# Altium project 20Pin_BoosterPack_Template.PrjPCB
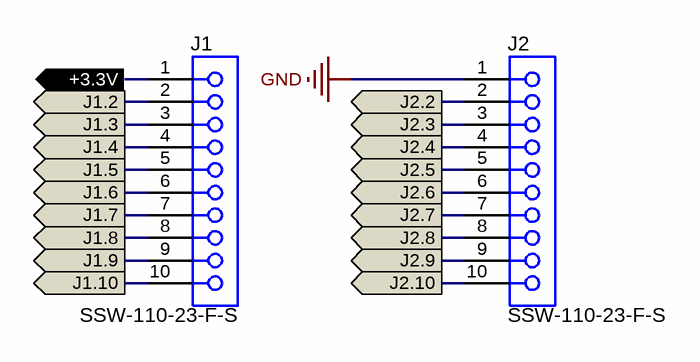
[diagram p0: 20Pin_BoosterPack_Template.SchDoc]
CopyrightYear: 2012; PCB_Layout: Who did the Layout?; PCB_Rev: E1; PRJ_Customer: Public Release; PRJ_Engineer: Enter name of project lead; PRJ_Number: XX####; PRJ_Title: Change in menu Project|Project Options|Parameters; SCH_Rev: E1; TechSupport: http://www.ti.com/support
1 sheet, 2 parts. Net scope: flat (ports and power ports of the same name join across sheets).
Board file: 20Pin_BoosterPack_Template.PcbDoc

## Sheet 20Pin_BoosterPack_Template.SchDoc
size 431 x 279 mm; Date: Not shown in title block; ApprovedBy: Not shown in title block; CheckedBy: Not shown in title block; Author: Not shown in title block; CompanyName: Not shown in title block; Engineer: Not shown in title block; Organization: Not shown in title block; Address1: Not shown in title block; Address2: Not shown in title block; Address3: Not shown in title block; Address4: Not shown in title block; DocumentNumber: 1; Revision: Use project parameter SCH_Rev; SheetNumber: 1; SheetTotal: 1; PageSetup: Record=PageOptions|CenterHorizontal=True|CenterVertical=True|PrintScale=1.00|XCorrection=1.00|YCorrection=1.00|PrintKind=0|BorderSize=5000000|LeftOffset=0|BottomOffset=0|Orientation=2|PaperLength=1000|PaperWidth=1000|Scale=100|PaperSource=15|PrintQuality=600|MediaType=1|DitherType=10|PaperKind=Letter|PrintScaleMode=1

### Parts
J1  SSW-110-23-F-S  [CONN_SSW-110-23-F-S]
J2  SSW-110-23-F-S  [CONN_SSW-110-23-F-S]

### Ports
+3.3V, J1.2, J1.3, J1.4, J1.5, J1.6, J1.7, J1.8, J1.9, J1.10, J2.2, J2.3, J2.4, J2.5, J2.6, J2.7, J2.8, J2.9, J2.10

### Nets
GND: J2.1
+3.3V: J1.1 ; port +3.3V
J1.2: J1.2 ; port J1.2
J1.3: J1.3 ; port J1.3
J1.4: J1.4 ; port J1.4
J1.5: J1.5 ; port J1.5
J1.6: J1.6 ; port J1.6
J1.7: J1.7 ; port J1.7
J1.8: J1.8 ; port J1.8
J1.9: J1.9 ; port J1.9
J1.10: J1.10 ; port J1.10
J2.2: J2.2 ; port J2.2
J2.3: J2.3 ; port J2.3
J2.4: J2.4 ; port J2.4
J2.5: J2.5 ; port J2.5
J2.6: J2.6 ; port J2.6
J2.7: J2.7 ; port J2.7
J2.8: J2.8 ; port J2.8
J2.9: J2.9 ; port J2.9
J2.10: J2.10 ; port J2.10

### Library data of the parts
J1 J2 = SSW-110-23-F-S: Connector, Receptacle, 100mil, 10x1, Gold plated, TH; Manufacturer: Samtec, Inc.; SymbolCreator: a0411947; U/M: EA

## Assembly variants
001: all parts fitted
